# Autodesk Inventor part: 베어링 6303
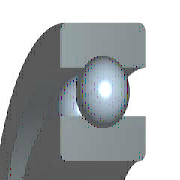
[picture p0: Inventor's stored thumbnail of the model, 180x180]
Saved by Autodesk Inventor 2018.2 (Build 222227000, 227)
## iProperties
IsCustomPart: 1
Created: 2012-02
Part Number: 베어링 6303
Material: 강철, 연강
Description: 단열 볼 베어링
Document SubType Name: Modeling
Standard: JIS B 1521
Designer: mdu-01
Standards Organization: JIS
Language: ko-KR
Size Designation: SKF 6303
Categories: <MemberInstance><Categories><Category DisplayName="샤프트 부품" InternalName="7f7aeb1f-a693-4053-b835-cee3144e0d98" Mnemonic="SHFT"><Category DisplayName="베어링" Inter
Density: 7.86 g/cm^3
Mass: 109.208 g
Surface Area: 91.3608 cm^2
Volume: 13.8942 cm^3
Appearance: 노란색
Author: mdu-01
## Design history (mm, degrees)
node "WorkPoint1"
node "WorkAxis1"
node "WorkPlane3"
node "WorkPlane4"
node "WorkPoint2"
body "Solid1"
node "스케치1"
revolve "회전1" stored, may be unused: angle "d6" = 360 deg
revolve "회전2" stored, may be unused: angle "d10" = 360 deg
node "스케치4"
revolve "회전3" stored, may be unused: angle "d16" = 360 deg
pattern_circular "원형 배열1" dims "d17" = 57.33333 (= msp_pocet), angle "d19" = 360 deg
fillet "모깎기1" dims "d20" = 1 (= r)
sketch "스케치2"
  geometry: L1 (8.5, 14)-(23.5, 14); L2 (8.5, 0)-(8.5, 14); L3 (23.5, 0)-(8.5, 0); L4 (23.5, 14)-(23.5, 0); L5 (0, 0)-(0, 20); L6 (0, 0)-(0, 20); L7 (-7.2, 0)-(43.2, 0) reference
  constraints: 12 end point, 3 vertical, 2 horizontal, 1 collinear, 1 other
  dimensions: "d1" = 17 diameter of L1.start L5 (= Diam); "d3" = 47 diameter of L1.end L5 (= DD); "d5" = 14 distance of L2.start L1.start (= msp_mdtd2)
sketch "스케치3"
  geometry: L1 (18.7, 14)-(18.7, 10.6); L2 (13.3, 14)-(18.7, 14); L3 (13.3, 10.6)-(13.3, 14); L4 (13.3, 0)-(13.3, 3.4); L5 (18.7, 0)-(13.3, 0); L6 (18.7, 3.4)-(18.7, 0); L7 (23.5, 0)-(-23.5, 0) reference; L8 (23.5, 14)-(-23.5, 14) reference; L9 (0, -42.29)-(0, 61.29); L10 (0, 82.007)-(0, -63.007) reference; A1 r 4.5 centre (16, 7) between (18.7, 3.4) and (18.7, 10.6); A2 r 4.5 centre (16, 7) between (13.3, 10.6) and (13.3, 3.4)
  constraints: 14 end point, 4 collinear, 4 point on circle, 4 vertical, 2 centre point, 2 concentric, 2 horizontal, 2 point on line
  dimensions: "d9" = 9 diameter of A1 (= msp_mdtd6); "d21" = 13.3 distance between parallel lines of L9 L4 (= 0.5 x msp_d1); "d22" = 16 distance from line of L9 A1.centre (= 0.5 x msp_ds); "d23" = 18.7 distance between parallel lines of L9 L6 (= 0.5 x msp_dd1)
sketch "스케치5"
  geometry: L1 (16, 2.5)-(16, 11.5); L2 (18.7, 0)-(-18.7, 0) reference; L3 (16, 2.5)-(16, 11.5); A1 r 4.5 centre (16, 7) between (16, 2.5) and (16, 11.5); A2 r 4.5 centre (16, 7) between (18.7, 3.4) and (18.7, 10.6) reference
  constraints: 4 end point, 2 point on circle, 1 centre point, 1 concentric, 1 vertical
  dimensions: "d13" = 0 horizontal distance of A1.centre L1.start; "d15" = 9.0001 diameter of A1 (computed from msp_mdtd6)
other parameters: "Diam" = 17 [user parameter; used in 3 equation terms], "DD" = 47 [user parameter; used in 3 equation terms], "B" = 14 [user parameter; used in 1 equation term], "r" = 1 [user parameter; used in 1 equation term], "msp_ds" = 32 (= 0.5 x Diam + 0.5 x DD) [user parameter; used in 5 equation terms], "msp_d0" = 9 (= -0.3 x Diam + 0.3 x DD) [user parameter; used in 4 equation terms], "msp_d1" = 26.6 (= msp_ds - 0.6 x msp_d0) [user parameter; used in 1 equation term], "msp_dd1" = 37.4 (= msp_ds + 0.6 x msp_d0) [user parameter; used in 1 equation term], "msp_pom" = 48 (= 1.5 x msp_ds) [user parameter; used in 1 equation term], "msp_mdtd2" = 14 (= B) [user parameter; used in 3 equation terms], "msp_mdtd4" = 32 (= msp_ds) [user parameter], "msp_mdtd6" = 9 (= msp_d0) [user parameter; used in 2 equation terms], "msp_mdtd7" = 7 (= 0.5 x msp_mdtd2) [user parameter], "msp_pocet" = 57.33333 (computed from msp_d0, msp_pom) [user parameter; used in 1 equation term], "d2" = 72 (derived), "d4" = 19 (derived), "d7" = 0, "d8" = 15.6 (derived), "d11" = -14 (computed from msp_mdtd2), "d12" = 0 (derived), "d14" = 15.6001 (derived), "d26" = 0, "d27" = 0, "d28" = 0, "d29" = 0, "d30" = 0
